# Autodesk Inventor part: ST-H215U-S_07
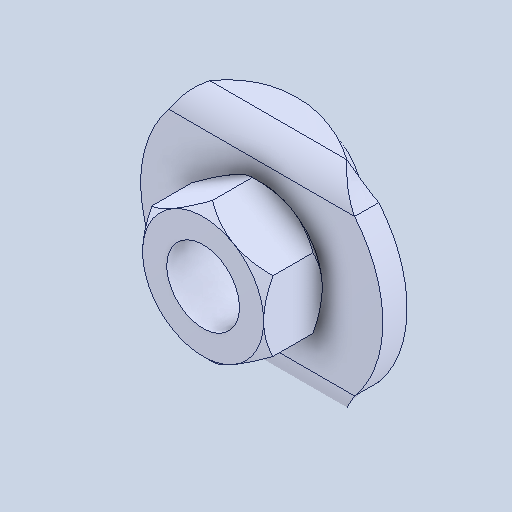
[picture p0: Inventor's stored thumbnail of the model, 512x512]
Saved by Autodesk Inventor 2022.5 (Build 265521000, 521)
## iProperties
Created: 2024-07
Part Number: ST-H215U-S_07
Material: 一般
Document SubType Name: Modeling
Designer: ImaoCorp
Density: 1 g/cm^3
Appearance: 既定
Author: ImaoCorp
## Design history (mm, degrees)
feature "ST-H215U-S_07"
node "ソリッド1"
